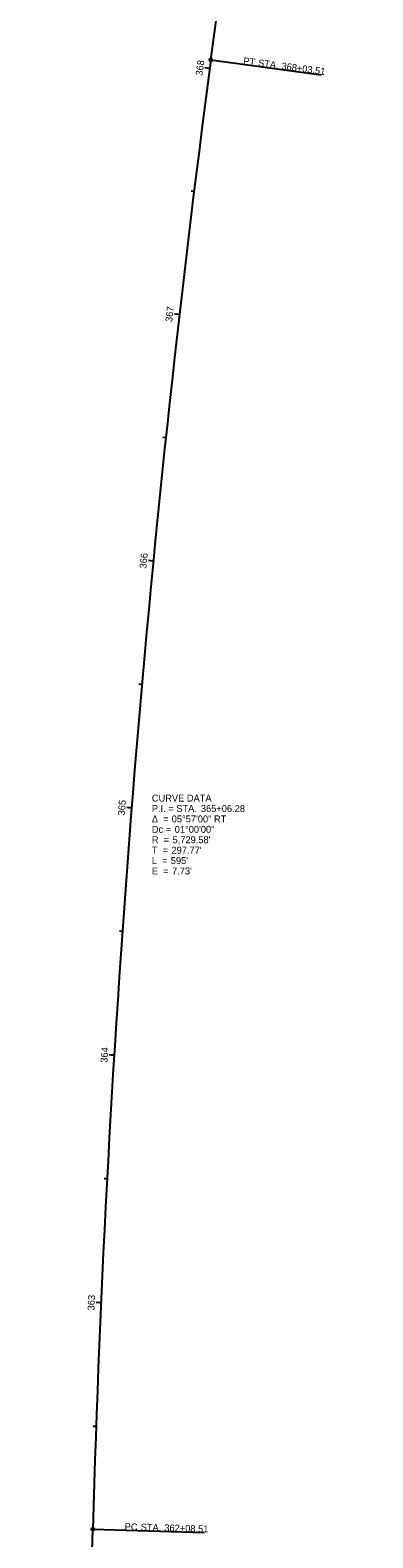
# Model space of a CAD drawing. Extents: x 1380776 to 1381901, y 503546 to 507267.
# Drawn here: x 1381762 to 1381900, y 506169 to 506778 of the extents above; entities that cross this region are included whole.
import ezdxf

# ---------------------------------------------------------------- set-up
doc = ezdxf.new("R2010")
doc.units = 0
for name, color, linetype in [('_CIVIL_CONSTRUCTION', 7, 'Continuous'), ('DR_P_Storm_Sewer', 7, 'Continuous'), ('DR_X_Cells', 7, 'Continuous'), ('DR_X_Storm_Sewer', 7, 'Continuous'), ('GK_Drainage_Nodes', 7, 'Continuous'), ('SC_Scratch1', 7, 'Continuous'), ('SC_Scratch3', 7, 'Continuous')]:
    doc.layers.add(name, color=color, linetype=linetype)

msp = doc.modelspace()

# ---------------------------------------------------------------- linework, layer by layer
at = {"layer": '_CIVIL_CONSTRUCTION'}
for p, q in [((1381834.43, 506762.13), (1381833.24, 506762.29)), ((1381834.89, 506765.61), (1381879.5, 506759.68)), ((1381822.18, 506662.88), (1381820.98, 506663.02)), ((1381811.66, 506563.44), (1381810.46, 506563.56)), ((1381802.87, 506463.83), (1381800.88, 506463.99)), ((1381795.83, 506364.08), (1381794.63, 506364.15)), ((1381790.52, 506264.22), (1381789.32, 506264.27)), ((1381787.2, 506172.8), (1381832.18, 506171.52))]:
    msp.add_line(p, q, dxfattribs=at)
for centre in [(1381834.89, 506765.61), (1381787.2, 506172.8)]:
    msp.add_circle(centre, 0.6, dxfattribs=at)
at = {"layer": 'DR_P_Storm_Sewer'}
for p, q in [((1381834.89, 506765.61), (1381879.5, 506759.68)), ((1381802.87, 506463.83), (1381801.67, 506463.92)), ((1381787.2, 506172.8), (1381832.18, 506171.52))]:
    msp.add_line(p, q, dxfattribs=at)
for centre in [(1381834.89, 506765.61), (1381787.2, 506172.8)]:
    msp.add_circle(centre, 0.6, dxfattribs=at)
at = {"layer": 'DR_X_Storm_Sewer'}
for p, q in [((1381834.43, 506762.13), (1381832.45, 506762.39)), ((1381834.89, 506765.61), (1381879.5, 506759.68)), ((1381828.09, 506712.53), (1381826.9, 506712.68)), ((1381822.18, 506662.88), (1381820.19, 506663.11)), ((1381816.7, 506613.18), (1381815.51, 506613.31)), ((1381811.66, 506563.44), (1381809.66, 506563.63)), ((1381807.05, 506513.65), (1381805.85, 506513.76)), ((1381802.87, 506463.83), (1381800.88, 506463.99)), ((1381799.13, 506413.97), (1381797.93, 506414.05)), ((1381795.83, 506364.08), (1381793.83, 506364.2)), ((1381792.96, 506314.16), (1381791.76, 506314.22)), ((1381790.52, 506264.22), (1381788.52, 506264.31)), ((1381788.52, 506214.26), (1381787.33, 506214.3)), ((1381787.2, 506172.8), (1381832.18, 506171.52))]:
    msp.add_line(p, q, dxfattribs=at)
for centre in [(1381834.89, 506765.61), (1381787.2, 506172.8)]:
    msp.add_circle(centre, 0.6, dxfattribs=at)
at = {"layer": 'SC_Scratch1'}
for p, q in [((1381834.89, 506765.61), (1381900.34, 507257.78)), ((1381761.87, 505279.88), (1381787.2, 506172.79))]:
    msp.add_line(p, q, dxfattribs=at)
msp.add_arc((1387514.47, 506010.32), 5729.58, 172.42509, 178.375046, dxfattribs=at)
msp.add_arc((1387514.47, 506010.32), 5729.58, 172.42509, 178.375046, dxfattribs=at)

# ---------------------------------------------------------------- texts
at = {"layer": '_CIVIL_CONSTRUCTION'}
for s, rotation, p in [('PT', 352.42509, (1381847.85, 506763.93)), (' STA. ', 352.42509, (1381852.81, 506763.27)), ('368+03.51', 352.42509, (1381863.29, 506761.88)), ('365', 85.46019, (1381800.07, 506460.73)), ('PC', 358.37505, (1381800.04, 506172.48)), (' STA. ', 358.37505, (1381805.47, 506172.32)), ('362+08.51', 358.37505, (1381816.05, 506172.02))]:
    msp.add_text(s, height=2.8, rotation=rotation, dxfattribs=at).set_placement(p)
at = {"layer": 'DR_P_Storm_Sewer'}
for s, rotation, p in [('PT', 352.42509, (1381847.85, 506763.93)), (' STA. ', 352.42509, (1381852.81, 506763.27)), ('368+03.51', 352.42509, (1381863.29, 506761.88)), ('PC', 358.37505, (1381800.04, 506172.48)), (' STA. ', 358.37505, (1381805.47, 506172.32)), ('362+08.51', 358.37505, (1381816.05, 506172.02))]:
    msp.add_text(s, height=2.8, rotation=rotation, dxfattribs=at).set_placement(p)
at = {"layer": 'DR_X_Cells'}
for s, p in [('CURVE DATA', (1381811.05, 506466.4)), ('P.I. = STA. ', (1381811.05, 506462.2)), ('365+06.28', (1381830.86, 506462.2)), ('Δ  = ', (1381811.05, 506458)), ('Dc = ', (1381811.05, 506453.8)), ('05°57\'00" RT', (1381819.07, 506458)), ('01°00\'00"', (1381820.29, 506453.8)), ('R  = ', (1381811.05, 506449.6)), ("5,729.58'", (1381819.41, 506449.6)), ('T  = ', (1381811.05, 506445.4)), ('L  = ', (1381811.05, 506441.2)), ("595'", (1381818.69, 506441.2)), ("297.77'", (1381818.98, 506445.4)), ('E  = ', (1381811.05, 506437)), ("7.73'", (1381819.2, 506437))]:
    msp.add_text(s, height=2.8, dxfattribs=at).set_placement(p)
at = {"layer": 'DR_X_Storm_Sewer'}
for s, rotation, p in [('PT', 352.42509, (1381847.85, 506763.93)), ('368', 82.46019, (1381831.47, 506759.16)), (' STA. ', 352.42509, (1381852.81, 506763.27)), ('368+03.51', 352.42509, (1381863.29, 506761.88)), ('367', 83.46019, (1381819.26, 506659.78)), ('366', 84.46019, (1381808.8, 506560.34)), ('365', 85.46019, (1381800.07, 506460.73)), ('364', 86.46019, (1381793.09, 506360.97)), ('363', 87.46019, (1381787.84, 506261.06)), ('PC', 358.37505, (1381800.04, 506172.48)), (' STA. ', 358.37505, (1381805.47, 506172.32)), ('362+08.51', 358.37505, (1381816.05, 506172.02))]:
    msp.add_text(s, height=2.8, rotation=rotation, dxfattribs=at).set_placement(p)
at = {"layer": 'GK_Drainage_Nodes'}
for s, p in [('CURVE DATA', (1381811.05, 506466.4)), ('P.I. = STA. ', (1381811.05, 506462.2)), ('365+06.28', (1381830.86, 506462.2)), ('Δ  = ', (1381811.05, 506458)), ('Dc = ', (1381811.05, 506453.8)), ('05°57\'00" RT', (1381819.07, 506458)), ('01°00\'00"', (1381820.29, 506453.8)), ('R  = ', (1381811.05, 506449.6)), ("5,729.58'", (1381819.41, 506449.6)), ('T  = ', (1381811.05, 506445.4)), ('L  = ', (1381811.05, 506441.2)), ("595'", (1381818.69, 506441.2)), ("297.77'", (1381818.98, 506445.4)), ('E  = ', (1381811.05, 506437)), ("7.73'", (1381819.2, 506437))]:
    msp.add_text(s, height=2.8, dxfattribs=at).set_placement(p)
at = {"layer": 'SC_Scratch3'}
for s, p in [('CURVE DATA', (1381811.05, 506466.4)), ('P.I. = STA. ', (1381811.05, 506462.2)), ('365+06.28', (1381830.86, 506462.2)), ('Δ  = ', (1381811.05, 506458)), ('Dc = ', (1381811.05, 506453.8)), ('05°57\'00" RT', (1381819.07, 506458)), ('01°00\'00"', (1381820.29, 506453.8)), ('R  = ', (1381811.05, 506449.6)), ("5,729.58'", (1381819.41, 506449.6)), ('T  = ', (1381811.05, 506445.4)), ('L  = ', (1381811.05, 506441.2)), ("595'", (1381818.69, 506441.2)), ("297.77'", (1381818.98, 506445.4)), ('E  = ', (1381811.05, 506437)), ("7.73'", (1381819.2, 506437))]:
    msp.add_text(s, height=2.8, dxfattribs=at).set_placement(p)

doc.saveas('drawing.dxf')
